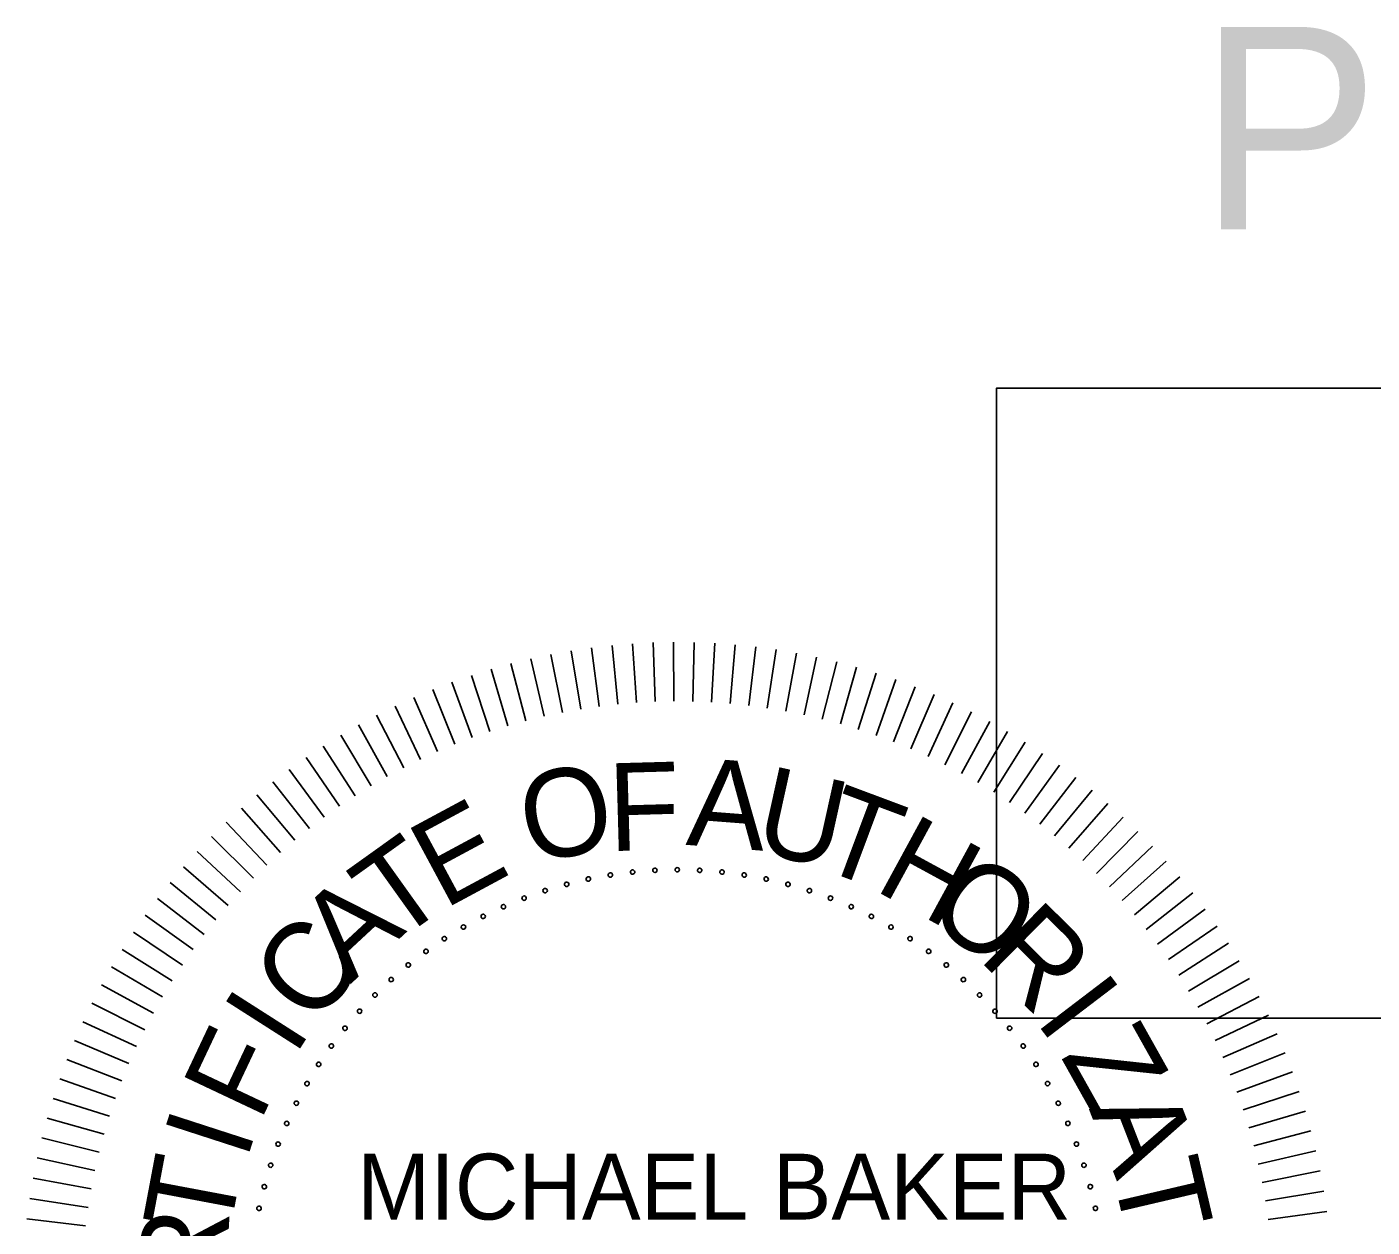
# Model space of a CAD drawing. Extents: x -0.96 to 2.36, y -0.12 to 0.92.
# Drawn here: x 1.1384 to 1.2247, y 0.1146 to 0.1916 of the extents above; entities that cross this region are included whole.
import ezdxf

# ---------------------------------------------------------------- set-up
doc = ezdxf.new("R2010")
doc.units = 0
for name, color, linetype in [('SHET_Border-Lines', 7, 'Continuous'), ('SHET_Stamp-Prelim', 7, 'Continuous'), ('STAMP_COA', 7, 'Continuous')]:
    doc.layers.add(name, color=color, linetype=linetype)

msp = doc.modelspace()

# ---------------------------------------------------------------- linework, layer by layer
at = {"layer": 'SHET_Border-Lines'}
msp.add_lwpolyline([(1.200633, 0.127997), (1.381804, 0.127997), (1.381804, 0.168449), (1.200633, 0.168449)], close=True, dxfattribs=at)
at = {"layer": 'STAMP_COA'}
for points in [[(1.177519, 0.148263), (1.17726, 0.152047)], [(1.17726, 0.152047), (1.177519, 0.148263)], [(1.178719, 0.148326), (1.178579, 0.152117)], [(1.178579, 0.152117), (1.178719, 0.148326)], [(1.179921, 0.148352), (1.1799, 0.152145)], [(1.1799, 0.152145), (1.179921, 0.148352)], [(1.181123, 0.148339), (1.181221, 0.152131)], [(1.181221, 0.152131), (1.181123, 0.148339)], [(1.182324, 0.148289), (1.182542, 0.152076)], [(1.182542, 0.152076), (1.182324, 0.148289)], [(1.172755, 0.147634), (1.172023, 0.151356)], [(1.172023, 0.151356), (1.172755, 0.147634)], [(1.173938, 0.147847), (1.173324, 0.15159)], [(1.173324, 0.15159), (1.173938, 0.147847)], [(1.175127, 0.148023), (1.174631, 0.151784)], [(1.174631, 0.151784), (1.175127, 0.148023)], [(1.176321, 0.148162), (1.175943, 0.151936)], [(1.175943, 0.151936), (1.176321, 0.148162)], [(1.183523, 0.148202), (1.183859, 0.15198)], [(1.183859, 0.15198), (1.183523, 0.148202)], [(1.184719, 0.148077), (1.185173, 0.151842)], [(1.185173, 0.151842), (1.184719, 0.148077)], [(1.18591, 0.147914), (1.186483, 0.151663)], [(1.186483, 0.151663), (1.18591, 0.147914)], [(1.187095, 0.147714), (1.187785, 0.151444)], [(1.187785, 0.151444), (1.187095, 0.147714)], [(1.188274, 0.147477), (1.189081, 0.151183)], [(1.189081, 0.151183), (1.188274, 0.147477)], [(1.169254, 0.146773), (1.168175, 0.150409)], [(1.168175, 0.150409), (1.169254, 0.146773)], [(1.170412, 0.147096), (1.169448, 0.150765)], [(1.169448, 0.150765), (1.170412, 0.147096)], [(1.171579, 0.147384), (1.170731, 0.151081)], [(1.170731, 0.151081), (1.171579, 0.147384)], [(1.189444, 0.147202), (1.190367, 0.150882)], [(1.190367, 0.150882), (1.189444, 0.147202)], [(1.190606, 0.146892), (1.191644, 0.15054)], [(1.191644, 0.15054), (1.190606, 0.146892)], [(1.166972, 0.146017), (1.165667, 0.149579)], [(1.165667, 0.149579), (1.166972, 0.146017)], [(1.168107, 0.146413), (1.166915, 0.150014)], [(1.166915, 0.150014), (1.168107, 0.146413)], [(1.191757, 0.146545), (1.192909, 0.150159)], [(1.192909, 0.150159), (1.191757, 0.146545)], [(1.192896, 0.146162), (1.194161, 0.149738)], [(1.194161, 0.149738), (1.192896, 0.146162)], [(1.164742, 0.14512), (1.163216, 0.148592)], [(1.163216, 0.148592), (1.164742, 0.14512)], [(1.16585, 0.145586), (1.164434, 0.149105)], [(1.164434, 0.149105), (1.16585, 0.145586)], [(1.194023, 0.145743), (1.1954, 0.149277)], [(1.1954, 0.149277), (1.194023, 0.145743)], [(1.195136, 0.145289), (1.196623, 0.148779)], [(1.196623, 0.148779), (1.195136, 0.145289)], [(1.163649, 0.144619), (1.162015, 0.148042)], [(1.162015, 0.148042), (1.163649, 0.144619)], [(1.196234, 0.144801), (1.19783, 0.148242)], [(1.19783, 0.148242), (1.196234, 0.144801)], [(1.161513, 0.143516), (1.159667, 0.146829)], [(1.159667, 0.146829), (1.161513, 0.143516)], [(1.162572, 0.144084), (1.160831, 0.147454)], [(1.160831, 0.147454), (1.162572, 0.144084)], [(1.197317, 0.144278), (1.19902, 0.147667)], [(1.19902, 0.147667), (1.197317, 0.144278)], [(1.198382, 0.143721), (1.200191, 0.147055)], [(1.200191, 0.147055), (1.198382, 0.143721)], [(1.160472, 0.142914), (1.158523, 0.146168)], [(1.158523, 0.146168), (1.160472, 0.142914)], [(1.19943, 0.143131), (1.201343, 0.146407)], [(1.201343, 0.146407), (1.19943, 0.143131)], [(1.15945, 0.14228), (1.1574, 0.145472)], [(1.1574, 0.145472), (1.15945, 0.14228)], [(1.200458, 0.142509), (1.202473, 0.145723)], [(1.202473, 0.145723), (1.200458, 0.142509)], [(1.158449, 0.141615), (1.1563, 0.14474)], [(1.1563, 0.14474), (1.158449, 0.141615)], [(1.201467, 0.141855), (1.203581, 0.145004)], [(1.203581, 0.145004), (1.201467, 0.141855)], [(1.202454, 0.141169), (1.204667, 0.14425)], [(1.204667, 0.14425), (1.202454, 0.141169)], [(1.15747, 0.140918), (1.155223, 0.143974)], [(1.20342, 0.140452), (1.205728, 0.143462)], [(1.205728, 0.143462), (1.20342, 0.140452)], [(1.156512, 0.140191), (1.154171, 0.143175)], [(1.154171, 0.143175), (1.156512, 0.140191)], [(1.204362, 0.139706), (1.206763, 0.142642)], [(1.206763, 0.142642), (1.204362, 0.139706)], [(1.155579, 0.139434), (1.153144, 0.142343)], [(1.153144, 0.142343), (1.155579, 0.139434)], [(1.20528, 0.13893), (1.207773, 0.14179)], [(1.207773, 0.14179), (1.20528, 0.13893)], [(1.154669, 0.138648), (1.152145, 0.14148)], [(1.152145, 0.14148), (1.154669, 0.138648)], [(1.208755, 0.140906), (1.206174, 0.138126)], [(1.206174, 0.138126), (1.208755, 0.140906)], [(1.153784, 0.137834), (1.151172, 0.140585)], [(1.151172, 0.140585), (1.153784, 0.137834)], [(1.209709, 0.139992), (1.207042, 0.137295)], [(1.207042, 0.137295), (1.209709, 0.139992)], [(1.152926, 0.136993), (1.150229, 0.13966)], [(1.150229, 0.13966), (1.152926, 0.136993)], [(1.152094, 0.136125), (1.149314, 0.138706)], [(1.149314, 0.138706), (1.152094, 0.136125)], [(1.210634, 0.139048), (1.207883, 0.136436)], [(1.207883, 0.136436), (1.210634, 0.139048)], [(1.15129, 0.135231), (1.148431, 0.137724)], [(1.148431, 0.137724), (1.15129, 0.135231)], [(1.211529, 0.138076), (1.208697, 0.135551)], [(1.208697, 0.135551), (1.211529, 0.138076)], [(1.150514, 0.134313), (1.147578, 0.136714)], [(1.147578, 0.136714), (1.150514, 0.134313)], [(1.212392, 0.137076), (1.209483, 0.134642)], [(1.209483, 0.134642), (1.212392, 0.137076)], [(1.149768, 0.133371), (1.146758, 0.135679)], [(1.146758, 0.135679), (1.149768, 0.133371)], [(1.213224, 0.136049), (1.21024, 0.133708)], [(1.21024, 0.133708), (1.213224, 0.136049)], [(1.214023, 0.134997), (1.210967, 0.13275)], [(1.210967, 0.13275), (1.214023, 0.134997)], [(1.149051, 0.132405), (1.14597, 0.134618)], [(1.14597, 0.134618), (1.149051, 0.132405)], [(1.214789, 0.13392), (1.211664, 0.131771)], [(1.211664, 0.131771), (1.214789, 0.13392)], [(1.148366, 0.131418), (1.145217, 0.133532)], [(1.145217, 0.133532), (1.148366, 0.131418)], [(1.147711, 0.130409), (1.144497, 0.132424)], [(1.144497, 0.132424), (1.147711, 0.130409)], [(1.215521, 0.13282), (1.212329, 0.13077)], [(1.212329, 0.13077), (1.215521, 0.13282)], [(1.147089, 0.129381), (1.143813, 0.131294)], [(1.143813, 0.131294), (1.147089, 0.129381)], [(1.216217, 0.131697), (1.212963, 0.129748)], [(1.212963, 0.129748), (1.216217, 0.131697)], [(1.216878, 0.130553), (1.213565, 0.128707)], [(1.213565, 0.128707), (1.216878, 0.130553)], [(1.146499, 0.128333), (1.143165, 0.130142)], [(1.143165, 0.130142), (1.146499, 0.128333)], [(1.145942, 0.127268), (1.142553, 0.128971)], [(1.142553, 0.128971), (1.145942, 0.127268)], [(1.217503, 0.129389), (1.214133, 0.127648)], [(1.214133, 0.127648), (1.217503, 0.129389)], [(1.218091, 0.128206), (1.214668, 0.126571)], [(1.214668, 0.126571), (1.218091, 0.128206)], [(1.14542, 0.126185), (1.141979, 0.127781)], [(1.141979, 0.127781), (1.14542, 0.126185)], [(1.218641, 0.127004), (1.215169, 0.125479)], [(1.215169, 0.125479), (1.218641, 0.127004)], [(1.144931, 0.125087), (1.141442, 0.126574)], [(1.141442, 0.126574), (1.144931, 0.125087)], [(1.144477, 0.123974), (1.140943, 0.125351)], [(1.140943, 0.125351), (1.144477, 0.123974)], [(1.219154, 0.125786), (1.215635, 0.12437)], [(1.215635, 0.12437), (1.219154, 0.125786)], [(1.219628, 0.124553), (1.216066, 0.123248)], [(1.216066, 0.123248), (1.219628, 0.124553)], [(1.144058, 0.122847), (1.140483, 0.124112)], [(1.140483, 0.124112), (1.144058, 0.122847)], [(1.143675, 0.121708), (1.140062, 0.12286)], [(1.140062, 0.12286), (1.143675, 0.121708)], [(1.220063, 0.123305), (1.216462, 0.122113)], [(1.216462, 0.122113), (1.220063, 0.123305)], [(1.220458, 0.122045), (1.216822, 0.120966)], [(1.216822, 0.120966), (1.220458, 0.122045)], [(1.143328, 0.120557), (1.13968, 0.121595)], [(1.13968, 0.121595), (1.143328, 0.120557)], [(1.143018, 0.119395), (1.139338, 0.120318)], [(1.139338, 0.120318), (1.143018, 0.119395)], [(1.220814, 0.120772), (1.217145, 0.119808)], [(1.217145, 0.119808), (1.220814, 0.120772)], [(1.22113, 0.119489), (1.217433, 0.118641)], [(1.217433, 0.118641), (1.22113, 0.119489)], [(1.142744, 0.118225), (1.139037, 0.119032)], [(1.139037, 0.119032), (1.142744, 0.118225)], [(1.142506, 0.117046), (1.138776, 0.117736)], [(1.138776, 0.117736), (1.142506, 0.117046)], [(1.221405, 0.118197), (1.217683, 0.117465)], [(1.217683, 0.117465), (1.221405, 0.118197)], [(1.221639, 0.116897), (1.217896, 0.116282)], [(1.217896, 0.116282), (1.221639, 0.116897)], [(1.142306, 0.115861), (1.138557, 0.116434)], [(1.138557, 0.116434), (1.142306, 0.115861)], [(1.142143, 0.11467), (1.138378, 0.115124)], [(1.138378, 0.115124), (1.142143, 0.11467)], [(1.221833, 0.115589), (1.218072, 0.115093)], [(1.218072, 0.115093), (1.221833, 0.115589)]]:
    msp.add_lwpolyline(points, dxfattribs=at)
for centre, start, end in [((1.17584, 0.137197), 9, 189), ((1.177265, 0.137385), 6, 186), ((1.177265, 0.137385), 186, 6), ((1.178698, 0.137498), 3, 183), ((1.178698, 0.137498), 183, 3), ((1.180135, 0.137535), 0, 180), ((1.180135, 0.137535), 180, 0), ((1.181571, 0.137498), 177, 357), ((1.181571, 0.137498), 357, 177), ((1.183004, 0.137385), 174, 354), ((1.183004, 0.137385), 354, 174), ((1.184429, 0.137197), 351, 171), ((1.17303, 0.1366), 15, 195), ((1.17303, 0.1366), 195, 15), ((1.174427, 0.136935), 12, 192), ((1.174427, 0.136935), 192, 12), ((1.17584, 0.137197), 189, 9), ((1.184429, 0.137197), 171, 351), ((1.185842, 0.136935), 168, 348), ((1.185842, 0.136935), 348, 168), ((1.187239, 0.1366), 165, 345), ((1.187239, 0.1366), 345, 165), ((1.170297, 0.135712), 21, 201), ((1.170297, 0.135712), 201, 21), ((1.171652, 0.136192), 18, 198), ((1.171652, 0.136192), 198, 18), ((1.188617, 0.136192), 162, 342), ((1.188617, 0.136192), 342, 162), ((1.189972, 0.135712), 159, 339), ((1.189972, 0.135712), 339, 159), ((1.16897, 0.135162), 24, 204), ((1.16897, 0.135162), 204, 24), ((1.191299, 0.135162), 156, 336), ((1.191299, 0.135162), 336, 156), ((1.16641, 0.133858), 30, 210), ((1.16641, 0.133858), 210, 30), ((1.167673, 0.134543), 27, 207), ((1.167673, 0.134543), 207, 27), ((1.192596, 0.134543), 153, 333), ((1.192596, 0.134543), 333, 153), ((1.193859, 0.133858), 150, 330), ((1.193859, 0.133858), 330, 150), ((1.165184, 0.133107), 33, 213), ((1.165184, 0.133107), 213, 33), ((1.195085, 0.133107), 147, 327), ((1.195085, 0.133107), 327, 147), ((1.164, 0.132293), 36, 216), ((1.164, 0.132293), 216, 36), ((1.196269, 0.132293), 144, 324), ((1.196269, 0.132293), 324, 144), ((1.16286, 0.131418), 39, 219), ((1.16286, 0.131418), 219, 39), ((1.197409, 0.131418), 141, 321), ((1.197409, 0.131418), 321, 141), ((1.161767, 0.130485), 42, 222), ((1.161767, 0.130485), 222, 42), ((1.198502, 0.130485), 138, 318), ((1.198502, 0.130485), 318, 138), ((1.160725, 0.129495), 45, 225), ((1.160725, 0.129495), 225, 45), ((1.199544, 0.129495), 135, 315), ((1.199544, 0.129495), 315, 135), ((1.159735, 0.128453), 48, 228), ((1.159735, 0.128453), 228, 48), ((1.200534, 0.128453), 132, 312), ((1.200534, 0.128453), 312, 132), ((1.158802, 0.12736), 51, 231), ((1.158802, 0.12736), 231, 51), ((1.201467, 0.12736), 129, 309), ((1.201467, 0.12736), 309, 129), ((1.157927, 0.12622), 54, 234), ((1.157927, 0.12622), 234, 54), ((1.202342, 0.12622), 126, 306), ((1.202342, 0.12622), 306, 126), ((1.157113, 0.125036), 57, 237), ((1.157113, 0.125036), 237, 57), ((1.203156, 0.125036), 123, 303), ((1.203156, 0.125036), 303, 123), ((1.156362, 0.12381), 60, 240), ((1.156362, 0.12381), 240, 60), ((1.203907, 0.12381), 120, 300), ((1.203907, 0.12381), 300, 120), ((1.155677, 0.122547), 63, 243), ((1.155677, 0.122547), 243, 63), ((1.204592, 0.122547), 117, 297), ((1.204592, 0.122547), 297, 117), ((1.155058, 0.12125), 66, 246), ((1.155058, 0.12125), 246, 66), ((1.205211, 0.12125), 114, 294), ((1.205211, 0.12125), 294, 114), ((1.154508, 0.119923), 69, 249), ((1.154508, 0.119923), 249, 69), ((1.205761, 0.119923), 111, 291), ((1.205761, 0.119923), 291, 111), ((1.154028, 0.118568), 72, 252), ((1.154028, 0.118568), 252, 72), ((1.206241, 0.118568), 108, 288), ((1.206241, 0.118568), 288, 108), ((1.15362, 0.11719), 75, 255), ((1.15362, 0.11719), 255, 75), ((1.206649, 0.11719), 105, 285), ((1.206649, 0.11719), 285, 105), ((1.153285, 0.115793), 78, 258), ((1.153285, 0.115793), 258, 78), ((1.206984, 0.115793), 102, 282), ((1.206984, 0.115793), 282, 102)]:
    msp.add_arc(centre, 0.000141, start, end, dxfattribs=at)

# ---------------------------------------------------------------- texts
at = {"layer": 'SHET_Stamp-Prelim'}
msp.add_text('PRELIMINARY', height=0.01299997, dxfattribs=at).set_placement((1.213606, 0.17864))
at = {"layer": 'STAMP_COA'}
for s, rotation, p in [('F', 1.58665, (1.175763, 0.138724)), ('A', 355.59545, (1.180647, 0.139138)), ('O', 10.72954, (1.170617, 0.137911)), ('U', 347.54807, (1.18491, 0.138736)), ('T', 339.50069, (1.188843, 0.137796)), ('E', 28.27898, (1.165147, 0.134959)), ('H', 331.45331, (1.192663, 0.13629)), ('T', 35.57245, (1.162002, 0.132778)), ('O', 323.40593, (1.195897, 0.134509)), ('A', 42.86593, (1.159141, 0.130175)), ('R', 315.35854, (1.199388, 0.131837)), ('C', 50.1594, (1.156771, 0.12736)), ('I', 307.31116, (1.20305, 0.127869)), ('I', 57.45288, (1.155547, 0.125476)), ('Z', 299.26378, (1.204705, 0.125574)), ('F', 64.74635, (1.153337, 0.121264)), ('I', 72.03983, (1.152464, 0.118788)), ('A', 291.2164, (1.206552, 0.122186)), ('T', 79.33331, (1.151344, 0.113934)), ('T', 283.16902, (1.208025, 0.1182)), ('R', 86.62678, (1.151086, 0.11021))]:
    msp.add_text(s, height=0.005634, rotation=rotation, dxfattribs=at).set_placement(p)
msp.add_text('MICHAEL BAKER', height=0.00422539, dxfattribs=at).set_placement((1.159575, 0.11508))

doc.saveas('drawing.dxf')
